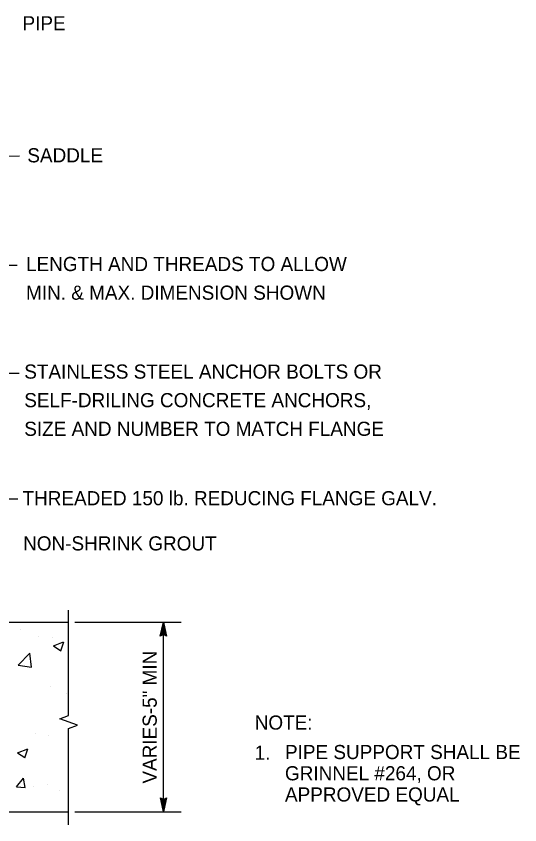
# Model space of a CAD drawing. Extents: x -123486 to -116575, y -107066 to -101122.
# Drawn here: x -117154.8 to -116941.4, y -102048.4 to -101705.4 of the extents above; entities that cross this region are included whole.
import ezdxf

# ---------------------------------------------------------------- set-up
doc = ezdxf.new("R2010")
doc.units = 0
for name, color, linetype in [('G-MARK', 7, 'Continuous'), ('G-TEXT', 7, 'Continuous'), ('Misc CnstDet(22)', 7, 'Continuous')]:
    doc.layers.add(name, color=color, linetype=linetype)

msp = doc.modelspace()

# ---------------------------------------------------------------- linework, layer by layer
at = {"layer": 'G-MARK'}
for p, q in [((-117130, -101962.44), (-117084.89, -101962.44)), ((-117092.39, -102042.91), (-117092.39, -101962.44)), ((-117130, -102042.91), (-117084.89, -102042.91))]:
    msp.add_line(p, q, dxfattribs=at)
for points in [[(-117213.09, -101755.84), (-117167.73, -101764.75), (-117153.45, -101764.72)], [(-117224.81, -101791.19), (-117170.56, -101811.07), (-117154.43, -101811.07)], [(-117209.58, -101941.35), (-117162.45, -101856.81), (-117153.54, -101856.81)], [(-117197.86, -101948.38), (-117171.69, -101910.1), (-117154.11, -101910.1)]]:
    msp.add_lwpolyline(points, dxfattribs=at)
at = {"layer": 'G-TEXT'}
for p, q in [((-117093.73, -101968.44), (-117092.39, -101962.44)), ((-117092.39, -101962.44), (-117092.39, -101962.44)), ((-117092.39, -101962.44), (-117091.06, -101968.44)), ((-117093.37, -101968.23), (-117092.39, -101963.82)), ((-117093.01, -101967.99), (-117092.39, -101965.21)), ((-117092.67, -101967.82), (-117092.39, -101966.59)), ((-117092.39, -101963.83), (-117091.42, -101968.21)), ((-117092.39, -101965.21), (-117091.77, -101968.03)), ((-117092.39, -101966.59), (-117092.13, -101967.8)), ((-117092.39, -101967.64), (-117093.73, -101968.44)), ((-117093.73, -101968.44), (-117093.73, -101968.44)), ((-117091.06, -101968.44), (-117092.39, -101967.64)), ((-117091.06, -101968.44), (-117091.06, -101968.44)), ((-117092.39, -102042.91), (-117093.72, -102036.91)), ((-117093.72, -102036.91), (-117093.72, -102036.91)), ((-117093.72, -102036.91), (-117092.39, -102037.71)), ((-117092.39, -102041.52), (-117093.36, -102037.15)), ((-117092.39, -102040.15), (-117093.01, -102037.32)), ((-117092.39, -102038.77), (-117092.65, -102037.56)), ((-117092.39, -102037.71), (-117091.05, -102036.91)), ((-117091.05, -102036.91), (-117092.39, -102042.91)), ((-117091.41, -102037.13), (-117092.39, -102041.53)), ((-117091.77, -102037.36), (-117092.39, -102040.15)), ((-117092.11, -102037.54), (-117092.39, -102038.77)), ((-117091.05, -102036.91), (-117091.05, -102036.91)), ((-117092.39, -102042.91), (-117092.39, -102042.91))]:
    msp.add_line(p, q, dxfattribs=at)
at = {"layer": 'Misc CnstDet(22)'}
for p, q in [((-117319.34, -101962.44), (-117132.62, -101962.44)), ((-117153.12, -101965.58), (-117153.12, -101965.58)), ((-117145.32, -101968.7), (-117145.32, -101968.7)), ((-117139.42, -101968.85), (-117139.42, -101968.85)), ((-117139.07, -101972.47), (-117134.7, -101970.79)), ((-117139.07, -101972.47), (-117135.96, -101974.57)), ((-117135.96, -101974.58), (-117134.69, -101970.8)), ((-117153.92, -101980.65), (-117149.05, -101975.57)), ((-117148.36, -101981.52), (-117149.05, -101975.58)), ((-117153.92, -101980.65), (-117148.36, -101981.51)), ((-117140.18, -101989.65), (-117140.18, -101989.65)), ((-117133.53, -101992.69), (-117133.53, -101992.69)), ((-117146.54, -102009.68), (-117146.54, -102009.68)), ((-117140.94, -102010.46), (-117140.94, -102010.46)), ((-117154.28, -102017.79), (-117149.9, -102016.11)), ((-117154.28, -102017.79), (-117151.17, -102019.89)), ((-117151.17, -102019.9), (-117149.9, -102016.12)), ((-117154.76, -102032.22), (-117151.75, -102028.63)), ((-117151.02, -102032.56), (-117151.75, -102028.64)), ((-117141.7, -102031.26), (-117141.7, -102031.26)), ((-117154.76, -102032.22), (-117151.02, -102032.55)), ((-117147.33, -102032.27), (-117147.33, -102032.27)), ((-117136.56, -102033.82), (-117136.56, -102033.82)), ((-117319.34, -102042.91), (-117132.62, -102042.91))]:
    msp.add_line(p, q, dxfattribs=at)
msp.add_lwpolyline([(-117132.62, -102048.38), (-117132.62, -102007.54), (-117128.87, -102006.17), (-117136.38, -102003.44), (-117132.62, -102002.07), (-117132.62, -101957.37)], dxfattribs=at)

# ---------------------------------------------------------------- texts
for s, p in [('PIPE', (-117152.15, -101711.43)), ('SADDLE', (-117150.11, -101767.43)), ('LENGTH AND THREADS TO ALLOW', (-117150.65, -101813.53)), ('MIN. & MAX. DIMENSION SHOWN', (-117150.65, -101825.68)), ('STAINLESS STEEL ANCHOR BOLTS OR', (-117151.4, -101859.16)), ('SELF-DRILING CONCRETE ANCHORS,', (-117151.4, -101871.27)), ('SIZE AND NUMBER TO MATCH FLANGE', (-117151.4, -101883.42)), ('THREADED 150 lb. REDUCING FLANGE GALV.', (-117152.15, -101912.86)), ('NON-SHRINK GROUT', (-117151.88, -101932.02)), ('NOTE:', (-117053.72, -102008)), ('1.', (-117053.72, -102020.77)), ('PIPE SUPPORT SHALL BE', (-117040.89, -102020.51)), ('GRINNEL #264, OR', (-117040.89, -102029.51)), ('APPROVED EQUAL', (-117040.89, -102038.51))]:
    msp.add_text(s, height=6, dxfattribs=at).set_placement(p)
msp.add_text('VARIES-5" MIN', height=6, rotation=90, dxfattribs=at).set_placement((-117095.24, -102030.89))

doc.saveas('drawing.dxf')
